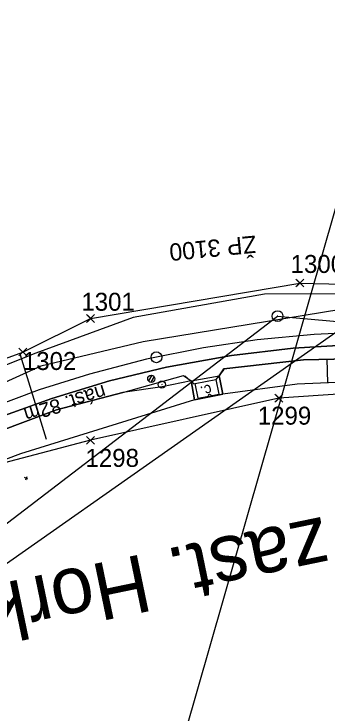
# Model space of a CAD drawing. Extents: x -738085 to -734426, y -1122197 to -1119748.
# Drawn here: x -737412.8 to -737369.1, y -1121471.2 to -1121373.8 of the extents above; entities that cross this region are included whole.
import ezdxf

# ---------------------------------------------------------------- set-up
doc = ezdxf.new("R2010")
doc.units = 0
for name, color, linetype in [('SŽDC', 7, 'Continuous'), ('Vrstva 1', 7, 'Continuous'), ('Vrstva 11', 7, 'Continuous'), ('Vrstva 12', 7, 'Continuous'), ('Vrstva 14', 7, 'Continuous'), ('Vrstva 17', 7, 'Continuous'), ('Vrstva 19', 7, 'Continuous'), ('Vrstva 23', 7, 'Continuous'), ('Vrstva 48', 7, 'Continuous'), ('Vrstva 49', 7, 'Continuous'), ('Vrstva 60', 7, 'Continuous'), ('Vrstva 63', 7, 'Continuous'), ('Vrstva 7', 7, 'Continuous')]:
    doc.layers.add(name, color=color, linetype=linetype)

msp = doc.modelspace()

# ---------------------------------------------------------------- linework, layer by layer
at = {"layer": 'SŽDC'}
for points in [[(-737421.67, -1121424.5), (-737411.54, -1121420.81), (-737402.12, -1121416.14), (-737373.02, -1121411.21), (-737354.93, -1121411.64)], [(-737357.45, -1121425.96), (-737375.94, -1121427.23), (-737402.13, -1121433.1)], [(-737402.13, -1121433.1), (-737424.51, -1121438.96), (-737426.47, -1121440.12)]]:
    msp.add_lwpolyline(points, dxfattribs=at)
at = {"layer": 'Vrstva 1'}
msp.add_lwpolyline([(-736738.787, -1121437.331), (-737330, -1121267.942), (-737406.294, -1121534.228), (-736815.081, -1121703.617)], close=True, dxfattribs=at)
msp.add_lwpolyline([(-737302.818, -1121423.992), (-737322.068, -1121421.435), (-737328.438, -1121420.593), (-737334.371, -1121419.848), (-737341.175, -1121419.077), (-737346.172, -1121418.626), (-737355.365, -1121418.093), (-737364.193, -1121418.049), (-737371.056, -1121418.37), (-737378.944, -1121419.134), (-737386.424, -1121420.242), (-737394.37, -1121421.821), (-737402.265, -1121423.869), (-737409.266, -1121426.074), (-737416.847, -1121428.911), (-737423.861, -1121431.965), (-737430.654, -1121435.335), (-737438.054, -1121439.528), (-737442.947, -1121442.622), (-737447.091, -1121445.439), (-737453.01, -1121449.85), (-737458.733, -1121454.549), (-737464.941, -1121460.218), (-737469.915, -1121465.238)], dxfattribs=at)
msp.add_lwpolyline([(-737302.818, -1121423.992), (-737322.068, -1121421.435), (-737328.438, -1121420.593), (-737334.371, -1121419.848), (-737341.175, -1121419.077), (-737346.172, -1121418.626), (-737355.365, -1121418.093), (-737364.193, -1121418.049), (-737371.056, -1121418.37), (-737378.944, -1121419.134), (-737386.424, -1121420.242), (-737394.37, -1121421.821), (-737402.265, -1121423.869), (-737409.266, -1121426.074), (-737416.847, -1121428.911), (-737423.861, -1121431.965), (-737430.654, -1121435.335), (-737438.054, -1121439.528), (-737442.947, -1121442.622), (-737447.091, -1121445.439), (-737453.01, -1121449.85), (-737458.733, -1121454.549), (-737464.941, -1121460.218), (-737469.915, -1121465.238)], dxfattribs=at)
at = {"layer": 'Vrstva 11'}
for p, q in [((-737393.602, -1121424.043), (-737394.072, -1121424.842)), ((-737393.283, -1121424.239), (-737393.746, -1121425.027))]:
    msp.add_line(p, q, dxfattribs=at)
msp.add_circle((-737393.683, -1121424.533), 0.5, dxfattribs=at)
at = {"layer": 'Vrstva 12'}
for p, q in [((-737383.749, -1121426.686), (-737383.749, -1121426.686)), ((-737387.69, -1121427.448), (-737387.69, -1121427.448))]:
    msp.add_line(p, q, dxfattribs=at)
for points in [[(-737383.749, -1121426.686), (-737387.69, -1121427.448), (-737388.136, -1121424.841), (-737384.256, -1121424.124), (-737383.749, -1121426.686)], [(-737388.136, -1121424.841), (-737387.69, -1121427.448), (-737383.749, -1121426.686), (-737384.256, -1121424.124)]]:
    msp.add_lwpolyline(points, dxfattribs=at)
at = {"layer": 'Vrstva 14'}
for points in [[(-737434.158, -1121439.207), (-737425.157, -1121434.445), (-737415.443, -1121430.128), (-737407.491, -1121427.257), (-737399.473, -1121424.819), (-737391.574, -1121422.902), (-737382.543, -1121421.309), (-737373.942, -1121420.283), (-737365.39, -1121419.766), (-737357.196, -1121419.694), (-737355.166, -1121419.793)], [(-737425.157, -1121434.445), (-737434.158, -1121439.207), (-737433.418, -1121440.485), (-737424.143, -1121435.606), (-737415.179, -1121431.98), (-737406.879, -1121428.878), (-737397.657, -1121426.455), (-737389.197, -1121424.096), (-737388.136, -1121424.841), (-737384.256, -1121424.124), (-737383.605, -1121423.164), (-737372.498, -1121421.888), (-737357.71, -1121421.577), (-737355.166, -1121419.793)], [(-737355.166, -1121419.793), (-737357.196, -1121419.694), (-737365.39, -1121419.766), (-737373.942, -1121420.283), (-737382.543, -1121421.309), (-737391.574, -1121422.902), (-737399.473, -1121424.819), (-737407.491, -1121427.257), (-737415.443, -1121430.128), (-737425.157, -1121434.445)]]:
    msp.add_lwpolyline(points, dxfattribs=at)
at = {"layer": 'Vrstva 17'}
for p, q in [((-737383.607, -1121423.221), (-737384.712, -1121424.64)), ((-737389.02, -1121424.144), (-737387.728, -1121425.219))]:
    msp.add_line(p, q, dxfattribs=at)
at = {"layer": 'Vrstva 19'}
msp.add_line((-737408.27, -1121432.997), (-737411.88, -1121421.246), dxfattribs=at)
at = {"layer": 'Vrstva 23'}
for q in [(-737387.592, -1121425.209), (-737384.288, -1121426.653)]:
    msp.add_line((-737387.168, -1121427.251), q, dxfattribs=at)
msp.add_lwpolyline([(-737387.592, -1121425.209), (-737384.707, -1121424.635), (-737384.288, -1121426.653)], dxfattribs=at)
at = {"layer": 'Vrstva 48'}
msp.add_line((-737369.253, -1121421.82), (-737369.183, -1121425.106), dxfattribs=at)
at = {"layer": 'Vrstva 49'}
for p, q in [((-737410.845, -1121438.502), (-737411.301, -1121438.294)), ((-737410.969, -1121438.17), (-737411.177, -1121438.626))]:
    msp.add_line(p, q, dxfattribs=at)
for points in [[(-737355.468, -1121412.323), (-737367.213, -1121412.694), (-737377.955, -1121412.777), (-737396.205, -1121415.993), (-737409.714, -1121420.959), (-737428.397, -1121428.396), (-737447.899, -1121439.996), (-737466.763, -1121457.312), (-737479.095, -1121469.068), (-737494.023, -1121491.429), (-737502.635, -1121510.598), (-737503.108, -1121511.735), (-737503.411, -1121512.475), (-737507.856, -1121528.05), (-737513.246, -1121551.434), (-737518.114, -1121577.507), (-737528.101, -1121607.824), (-737533.622, -1121619.302), (-737538.45, -1121627.339), (-737537.777, -1121628.499)], [(-737354.911, -1121414.279), (-737363.928, -1121414.852), (-737364.757, -1121414.891), (-737367.307, -1121414.876), (-737377.515, -1121416.552), (-737394.826, -1121419.38), (-737409.027, -1121422.784), (-737424.524, -1121429.773), (-737425.257, -1121430.092), (-737426.75, -1121430.355), (-737446.443, -1121441.666), (-737466.183, -1121457.869), (-737471.182, -1121463.445), (-737471.745, -1121464.014), (-737477.78, -1121470.255), (-737492.767, -1121492.111), (-737501.926, -1121510.887), (-737502.368, -1121512.037), (-737502.67, -1121512.778), (-737507.856, -1121528.05)], [(-737356.801, -1121427.289), (-737356.872, -1121423.391), (-737357.71, -1121421.577), (-737372.498, -1121421.888), (-737383.605, -1121423.164), (-737384.256, -1121424.124), (-737383.749, -1121426.686)], [(-737387.69, -1121427.448), (-737388.136, -1121424.841), (-737392.187, -1121425.634), (-737397.657, -1121426.455), (-737406.879, -1121428.878), (-737415.179, -1121431.98), (-737424.143, -1121435.606), (-737433.418, -1121440.485), (-737435.107, -1121440.571)], [(-737359.408, -1121428.568), (-737359.258, -1121424.661), (-737373.387, -1121425.294), (-737383.749, -1121426.686)], [(-737387.69, -1121427.448), (-737411.856, -1121434.997), (-737433.881, -1121443.296)]]:
    msp.add_lwpolyline(points, dxfattribs=at)
at = {"layer": 'Vrstva 60'}
for p, q in [((-737372.57, -1121411.66), (-737373.57, -1121410.66)), ((-737372.57, -1121410.76), (-737373.57, -1121411.76)), ((-737373.47, -1121411.66), (-737372.47, -1121410.66)), ((-737373.47, -1121410.76), (-737372.47, -1121411.76)), ((-737373.02, -1121411.21), (-737373.02, -1121411.21)), ((-737401.67, -1121416.59), (-737402.67, -1121415.59)), ((-737401.67, -1121415.69), (-737402.67, -1121416.69)), ((-737402.57, -1121416.59), (-737401.57, -1121415.59)), ((-737402.57, -1121415.69), (-737401.57, -1121416.69)), ((-737402.12, -1121416.14), (-737402.12, -1121416.14)), ((-737411.09, -1121421.26), (-737412.09, -1121420.26)), ((-737411.09, -1121420.36), (-737412.09, -1121421.36)), ((-737411.99, -1121421.26), (-737410.99, -1121420.26)), ((-737411.99, -1121420.36), (-737410.99, -1121421.36)), ((-737411.54, -1121420.81), (-737411.54, -1121420.81)), ((-737375.49, -1121427.68), (-737376.49, -1121426.68)), ((-737375.49, -1121426.78), (-737376.49, -1121427.78)), ((-737376.39, -1121427.68), (-737375.39, -1121426.68)), ((-737376.39, -1121426.78), (-737375.39, -1121427.78)), ((-737375.94, -1121427.23), (-737375.94, -1121427.23)), ((-737401.68, -1121433.55), (-737402.68, -1121432.55)), ((-737401.68, -1121432.65), (-737402.68, -1121433.65)), ((-737402.58, -1121433.55), (-737401.58, -1121432.55)), ((-737402.58, -1121432.65), (-737401.58, -1121433.65)), ((-737402.13, -1121433.1), (-737402.13, -1121433.1))]:
    msp.add_line(p, q, dxfattribs=at)
at = {"layer": 'Vrstva 63'}
for p, q in [((-737502.707, -1121512.73), (-737376.128, -1121415.817)), ((-737502.606, -1121512.637), (-737364.617, -1121415.627)), ((-737376.078, -1121415.812), (-737376.178, -1121415.822)), ((-737376.128, -1121415.817), (-737220.606, -1121429.814))]:
    msp.add_line(p, q, dxfattribs=at)
msp.add_circle((-737376.128, -1121415.817), 0.756, dxfattribs=at)
at = {"layer": 'Vrstva 7'}
msp.add_line((-737392.17, -1121425.334), (-737392.268, -1121425.354), dxfattribs=at)
for centre, radius in [((-737392.974, -1121421.544), 0.75), ((-737392.974, -1121421.544), 0.75), ((-737392.219, -1121425.344), 0.5)]:
    msp.add_circle(centre, radius, dxfattribs=at)

# ---------------------------------------------------------------- texts
at = {"layer": 'Vrstva 14'}
msp.add_text('nást. 82m', height=2, rotation=196.91273, dxfattribs=at).set_placement((-737400.343, -1121425.324))
at = {"layer": 'Vrstva 23'}
for s, height, rotation, p in [('č.', 1.5, 196.85005, (-737385.51, -1121425.245)), ('zast. Horky u Tábora', 8, 191.73019, (-737369.8, -1121443.687))]:
    msp.add_text(s, height=height, rotation=rotation, dxfattribs=at).set_placement(p)
at = {"layer": 'Vrstva 60'}
for s, p in [('1300', (-737374.309, -1121409.804)), ('1301', (-737403.409, -1121415.067)), ('1302', (-737411.54, -1121423.31)), ('1299', (-737378.879, -1121430.917)), ('1298', (-737402.833, -1121436.793))]:
    msp.add_text(s, height=2.5, dxfattribs=at).set_placement(p)
at = {"layer": 'Vrstva 63'}
msp.add_text('ŽP 3100', height=2.4, rotation=185.53218, dxfattribs=at).set_placement((-737379.2, -1121404.592))

doc.saveas('drawing.dxf')
